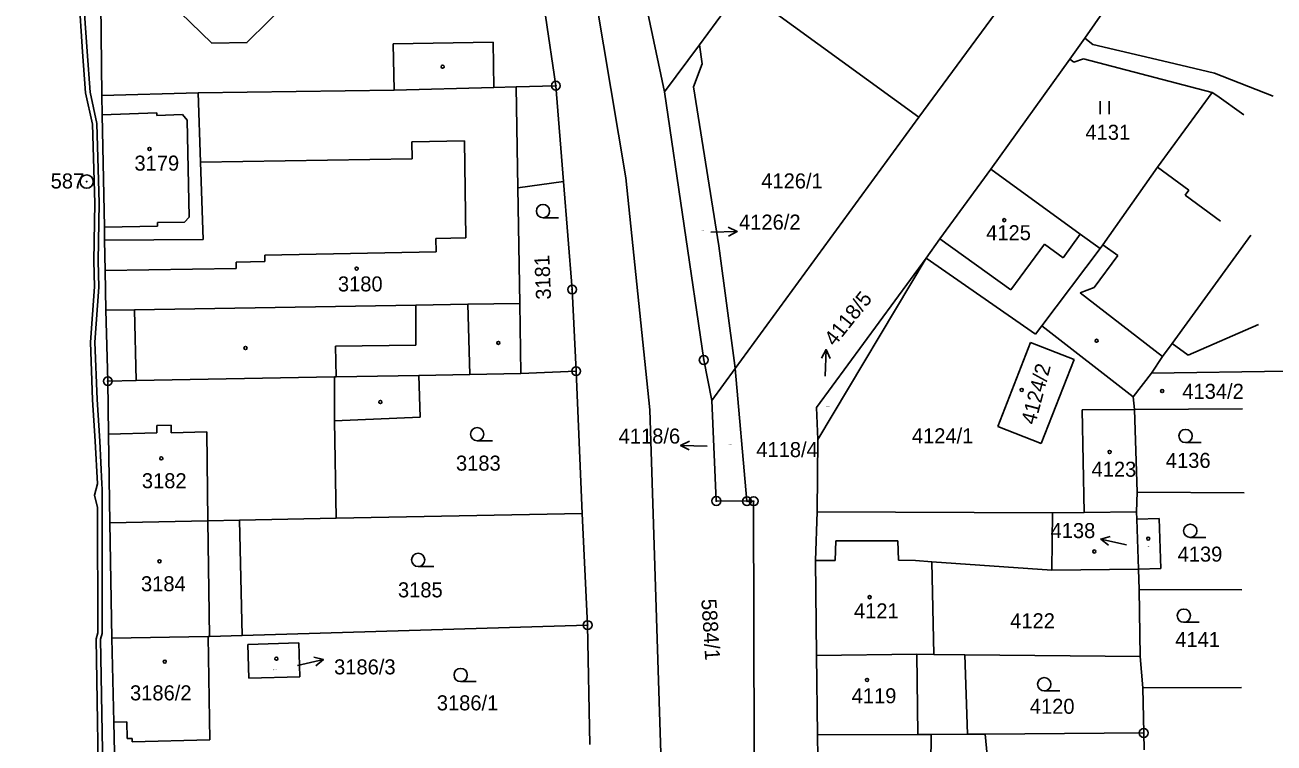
# Model space of a CAD drawing. Extents: x -735092 to -733385, y -1122435 to -1118992.
# Drawn here: x -734445.9 to -734304.7, y -1120246.4 to -1120165.2 of the extents above; entities that cross this region are included whole.
import ezdxf

# ---------------------------------------------------------------- set-up
doc = ezdxf.new("R2010")
doc.units = 0
for name, color, linetype in [('Vrstva 1', 7, 'Continuous'), ('Vrstva 10', 7, 'Continuous'), ('Vrstva 16', 7, 'Continuous'), ('Vrstva 17', 7, 'Continuous'), ('Vrstva 18', 7, 'Continuous'), ('Vrstva 19', 7, 'Continuous'), ('Vrstva 25', 7, 'Continuous'), ('Vrstva 27', 7, 'Continuous'), ('Vrstva 4', 7, 'Continuous')]:
    doc.layers.add(name, color=color, linetype=linetype)

msp = doc.modelspace()

# ---------------------------------------------------------------- linework, layer by layer
at = {"layer": 'Vrstva 1'}
for points in [[(-734388.19, -1120156.22), (-734385.85, -1120172.09)], [(-734377.07, -1120156.21), (-734373.55, -1120172.79)], [(-734369.62, -1120167.46), (-734364.89, -1120161.04)], [(-734364.89, -1120161.04), (-734344.83, -1120175.64)], [(-734437.28, -1120162.84), (-734437.16, -1120173.21)], [(-734344.83, -1120175.64), (-734335.61, -1120163.18)], [(-734326.04, -1120166.73), (-734323.79, -1120163.47)], [(-734373.55, -1120172.79), (-734369.62, -1120167.46)], [(-734369.62, -1120167.46), (-734369.29, -1120169.62)], [(-734327.74, -1120169.11), (-734326.04, -1120166.73)], [(-734326.04, -1120166.73), (-734325.13, -1120167.42)], [(-734325.13, -1120167.42), (-734316.63, -1120169.42)], [(-734336.67, -1120181.53), (-734327.74, -1120169.11)], [(-734327.74, -1120169.11), (-734327.31, -1120169.43)], [(-734327.31, -1120169.43), (-734326.19, -1120169.06)], [(-734326.19, -1120169.06), (-734311.66, -1120172.86)], [(-734369.29, -1120169.62), (-734370.29, -1120172.21)], [(-734316.63, -1120169.42), (-734311.38, -1120170.66)], [(-734311.38, -1120170.66), (-734304.75, -1120173.28)], [(-734390.34, -1120172.22), (-734385.85, -1120172.09)], [(-734385.85, -1120172.09), (-734384.98, -1120182.94)], [(-734437.16, -1120173.21), (-734426.3, -1120172.91)], [(-734437.16, -1120173.21), (-734437.13, -1120175.37)], [(-734426.3, -1120172.91), (-734404.13, -1120172.58)], [(-734426.3, -1120172.91), (-734426.02, -1120180.73)], [(-734404.13, -1120172.58), (-734392.87, -1120172.29)], [(-734392.87, -1120172.29), (-734390.34, -1120172.22)], [(-734373.55, -1120172.79), (-734369.13, -1120203.11)], [(-734370.29, -1120172.21), (-734367.41, -1120190.22)], [(-734317.82, -1120181.32), (-734311.66, -1120172.86)], [(-734311.66, -1120172.86), (-734311.14, -1120173.22)], [(-734311.14, -1120173.22), (-734308.07, -1120175.39)], [(-734437.13, -1120175.37), (-734436.88, -1120188.08)], [(-734365.59, -1120204.07), (-734344.83, -1120175.64)], [(-734426.02, -1120180.73), (-734425.71, -1120189.47)], [(-734342.45, -1120189.42), (-734336.67, -1120181.53)], [(-734336.67, -1120181.53), (-734326.56, -1120188.87)], [(-734324.02, -1120190.1), (-734317.82, -1120181.32)], [(-734390.15, -1120183.65), (-734384.98, -1120182.94)], [(-734384.98, -1120182.94), (-734384.01, -1120195.15)], [(-734390.15, -1120183.65), (-734389.94, -1120196.71)], [(-734436.88, -1120188.08), (-734436.86, -1120189.58)], [(-734326.56, -1120188.87), (-734324.31, -1120190.51)], [(-734316.19, -1120201.26), (-734307.27, -1120189.01)], [(-734436.86, -1120189.58), (-734425.71, -1120189.47)], [(-734436.86, -1120189.58), (-734436.79, -1120192.99)], [(-734367.41, -1120190.22), (-734365.63, -1120203.75)], [(-734344, -1120191.6), (-734342.45, -1120189.42)], [(-734330.9, -1120199.24), (-734324.31, -1120190.51)], [(-734324.31, -1120190.51), (-734324.02, -1120190.1)], [(-734356.4, -1120208.47), (-734344, -1120191.6)], [(-734356.22, -1120212.09), (-734344, -1120191.6)], [(-734344, -1120191.6), (-734331.62, -1120200.2)], [(-734436.79, -1120192.99), (-734436.71, -1120197.49)], [(-734384.01, -1120195.15), (-734383.56, -1120204.38)], [(-734436.71, -1120197.49), (-734436.5, -1120205.51)], [(-734389.94, -1120196.71), (-734389.81, -1120204.63)], [(-734331.62, -1120200.2), (-734330.9, -1120199.24)], [(-734330.9, -1120199.24), (-734320.57, -1120207.27)], [(-734314.36, -1120202.56), (-734306.41, -1120199.09)], [(-734335.88, -1120210.65), (-734332.2, -1120201.13)], [(-734332.2, -1120201.13), (-734327.26, -1120203.06)], [(-734317.26, -1120202.73), (-734316.19, -1120201.26)], [(-734316.19, -1120201.26), (-734314.36, -1120202.56)], [(-734369.13, -1120203.11), (-734368.23, -1120207.69)], [(-734330.97, -1120212.57), (-734327.26, -1120203.06)], [(-734318.52, -1120204.62), (-734317.26, -1120202.73)], [(-734395.58, -1120204.74), (-734389.81, -1120204.63)], [(-734389.81, -1120204.63), (-734383.56, -1120204.38)], [(-734383.56, -1120204.38), (-734382.86, -1120220.49)], [(-734368.23, -1120207.69), (-734365.59, -1120204.07)], [(-734365.63, -1120203.75), (-734365.59, -1120204.07)], [(-734364.25, -1120219.08), (-734365.59, -1120204.07)], [(-734320.57, -1120207.27), (-734318.52, -1120204.62)], [(-734318.52, -1120204.62), (-734303.17, -1120204.36)], [(-734436.5, -1120205.51), (-734433.3, -1120205.45)], [(-734436.5, -1120205.51), (-734436.41, -1120211.49)], [(-734433.3, -1120205.45), (-734410.88, -1120205.03)], [(-734410.88, -1120205.03), (-734410.69, -1120205.02)], [(-734410.69, -1120205.02), (-734401.34, -1120204.85)], [(-734401.34, -1120204.85), (-734395.58, -1120204.74)], [(-734401.34, -1120204.85), (-734401.18, -1120209.59)], [(-734320.57, -1120207.27), (-734320.45, -1120208.7)], [(-734368.23, -1120207.69), (-734367.71, -1120219.06)], [(-734356.4, -1120208.47), (-734356.22, -1120212.09)], [(-734326.34, -1120208.76), (-734320.45, -1120208.7)], [(-734326.34, -1120208.76), (-734326.14, -1120220.37)], [(-734320.45, -1120208.7), (-734308.22, -1120208.63)], [(-734320.45, -1120208.7), (-734320.14, -1120218.07)], [(-734410.88, -1120210), (-734401.18, -1120209.59)], [(-734410.88, -1120210), (-734410.68, -1120221.02)], [(-734436.41, -1120211.49), (-734436.26, -1120221.53)], [(-734335.88, -1120210.65), (-734330.97, -1120212.57)], [(-734356.3, -1120220.29), (-734356.22, -1120212.09)], [(-734320.2, -1120220.27), (-734320.14, -1120218.07)], [(-734320.14, -1120218.07), (-734308.03, -1120218.15)], [(-734367.71, -1120219.06), (-734364.25, -1120219.08)], [(-734364.25, -1120219.08), (-734363.49, -1120219.09)], [(-734363.49, -1120219.09), (-734363.36, -1120275.36)], [(-734436.26, -1120221.53), (-734425.18, -1120221.3)], [(-734436.26, -1120221.53), (-734436.06, -1120234.59)], [(-734425.18, -1120221.3), (-734421.63, -1120221.23)], [(-734421.63, -1120221.23), (-734410.68, -1120221.02)], [(-734421.63, -1120221.23), (-734421.33, -1120234.26)], [(-734410.68, -1120221.02), (-734382.86, -1120220.49)], [(-734382.86, -1120220.49), (-734382.26, -1120233.1)], [(-734356.51, -1120225.79), (-734356.3, -1120220.29)], [(-734356.3, -1120220.29), (-734329.69, -1120220.41)], [(-734329.69, -1120220.41), (-734326.14, -1120220.37)], [(-734326.14, -1120220.37), (-734320.2, -1120220.27)], [(-734320.2, -1120220.27), (-734320.17, -1120221.12)], [(-734320.17, -1120221.12), (-734317.65, -1120221.03)], [(-734320.17, -1120221.12), (-734319.98, -1120226.79)], [(-734317.65, -1120221.03), (-734317.46, -1120226.7)], [(-734356.51, -1120225.79), (-734356.37, -1120236.52)], [(-734343.34, -1120225.93), (-734343.11, -1120236.41)], [(-734343.34, -1120225.93), (-734329.78, -1120226.87)], [(-734329.78, -1120226.87), (-734319.98, -1120226.79)], [(-734319.98, -1120226.79), (-734317.46, -1120226.7)], [(-734319.98, -1120226.79), (-734319.9, -1120229.06)], [(-734319.9, -1120229.06), (-734319.8, -1120236.66)], [(-734319.9, -1120229.06), (-734308.29, -1120229.12)], [(-734425.01, -1120234.37), (-734421.33, -1120234.26)], [(-734421.33, -1120234.26), (-734382.26, -1120233.1)], [(-734382.26, -1120233.1), (-734381.99, -1120246.61)], [(-734436.06, -1120234.59), (-734425.16, -1120234.37)], [(-734436.06, -1120234.59), (-734435.82, -1120244.07)], [(-734425.16, -1120234.37), (-734425.01, -1120234.37)], [(-734425.16, -1120234.37), (-734424.97, -1120246.07)], [(-734420.68, -1120235.29), (-734414.89, -1120235.1)], [(-734420.68, -1120235.29), (-734420.57, -1120239.09)], [(-734414.89, -1120235.1), (-734414.78, -1120238.93)], [(-734356.37, -1120236.52), (-734345.04, -1120236.39)], [(-734356.37, -1120236.52), (-734356.26, -1120245.51)], [(-734345.04, -1120236.39), (-734343.11, -1120236.41)], [(-734343.11, -1120236.41), (-734339.6, -1120236.45)], [(-734339.6, -1120236.45), (-734319.8, -1120236.66)], [(-734339.6, -1120236.45), (-734339.32, -1120245.43)], [(-734319.8, -1120236.66), (-734319.48, -1120240.2)], [(-734420.57, -1120239.09), (-734414.78, -1120238.93)], [(-734319.48, -1120240.2), (-734308.35, -1120240.15)], [(-734319.48, -1120240.2), (-734319.39, -1120245.3)], [(-734435.82, -1120244.07), (-734434.35, -1120244.04)], [(-734435.82, -1120244.07), (-734435.73, -1120247.52)], [(-734434.35, -1120244.04), (-734434.31, -1120245.94)], [(-734356.26, -1120245.51), (-734344.93, -1120245.47)], [(-734356.26, -1120245.51), (-734356.25, -1120248.09)], [(-734344.93, -1120245.47), (-734343.43, -1120245.46)], [(-734343.43, -1120245.46), (-734339.32, -1120245.43)], [(-734339.32, -1120245.43), (-734337.32, -1120245.42)], [(-734337.32, -1120245.42), (-734319.39, -1120245.3)], [(-734337.32, -1120245.42), (-734337.02, -1120248.59)], [(-734319.39, -1120245.3), (-734319.34, -1120247.21)], [(-734434.31, -1120245.94), (-734433.74, -1120245.92)], [(-734433.74, -1120245.92), (-734433.73, -1120246.29)], [(-734433.73, -1120246.29), (-734424.97, -1120246.07)]]:
    msp.add_lwpolyline(points, dxfattribs=at)
at = {"layer": 'Vrstva 10'}
for points in [[(-734377.94, -1120182.5), (-734382.16, -1120157.32)], [(-734377.94, -1120182.5), (-734375.24, -1120208.76)], [(-734375.24, -1120208.76), (-734373.89, -1120249.96)]]:
    msp.add_lwpolyline(points, dxfattribs=at)
at = {"layer": 'Vrstva 25'}
for points in [[(-734324.317, -1120175.325), (-734324.317, -1120173.825)], [(-734323.283, -1120175.325), (-734323.283, -1120173.825)], [(-734387.3, -1120187.02), (-734385.55, -1120187.02)], [(-734368.34, -1120188.67), (-734365.342, -1120188.571)], [(-734366.358, -1120188.104), (-734365.342, -1120188.571), (-734366.325, -1120189.103)], [(-734355.829, -1120202.924), (-734355.296, -1120201.942), (-734354.831, -1120202.959)], [(-734355.4, -1120204.94), (-734355.296, -1120201.942)], [(-734394.75, -1120212.25), (-734393, -1120212.25)], [(-734370.763, -1120213.293), (-734371.748, -1120212.767), (-734370.735, -1120212.295)], [(-734368.75, -1120212.85), (-734371.748, -1120212.767)], [(-734314.66, -1120212.46), (-734312.91, -1120212.46)], [(-734323.38, -1120224.072), (-734324.251, -1120223.371), (-734323.167, -1120223.096)], [(-734321.32, -1120224.01), (-734324.251, -1120223.371)], [(-734314.13, -1120223.18), (-734312.38, -1120223.18)], [(-734401.41, -1120226.48), (-734399.66, -1120226.48)], [(-734314.86, -1120232.78), (-734313.11, -1120232.78)], [(-734415.04, -1120237.68), (-734412.125, -1120236.975)], [(-734413.214, -1120236.724), (-734412.125, -1120236.975), (-734412.979, -1120237.695)], [(-734396.61, -1120239.49), (-734394.86, -1120239.49)], [(-734330.63, -1120240.54), (-734328.88, -1120240.54)]]:
    msp.add_lwpolyline(points, dxfattribs=at)
for centre, radius in [((-734398.65, -1120169.95), 0.175), ((-734385.85, -1120172.09), 0.499), ((-734385.85, -1120172.09), 0.0314), ((-734431.79, -1120179.25), 0.175), ((-734438.89, -1120182.94), 0.75), ((-734438.89, -1120182.94), 0.032), ((-734387.3, -1120186.27), 0.75), ((-734335.16, -1120187.3), 0.175), ((-734408.37, -1120192.78), 0.175), ((-734384.01, -1120195.15), 0.499), ((-734384.01, -1120195.15), 0.0318), ((-734420.93, -1120201.76), 0.175), ((-734392.35, -1120201.18), 0.175), ((-734324.71, -1120200.94), 0.175), ((-734369.13, -1120203.11), 0.5), ((-734369.13, -1120203.11), 0.032), ((-734383.56, -1120204.38), 0.5), ((-734383.56, -1120204.38), 0.5), ((-734383.56, -1120204.38), 0.032), ((-734383.56, -1120204.38), 0.032), ((-734436.5, -1120205.51), 0.5), ((-734436.5, -1120205.51), 0.032), ((-734333.18, -1120206.5), 0.175), ((-734317.3, -1120206.63), 0.175), ((-734405.69, -1120207.87), 0.175), ((-734394.75, -1120211.5), 0.75), ((-734314.66, -1120211.71), 0.75), ((-734430.46, -1120214.24), 0.175), ((-734323.25, -1120213.52), 0.175), ((-734367.71, -1120219.06), 0.5), ((-734364.25, -1120219.08), 0.5), ((-734363.49, -1120219.09), 0.5), ((-734367.71, -1120219.06), 0.032), ((-734364.25, -1120219.08), 0.032), ((-734363.49, -1120219.09), 0.032), ((-734314.13, -1120222.43), 0.75), ((-734318.88, -1120223.32), 0.175), ((-734430.66, -1120225.88), 0.175), ((-734401.41, -1120225.73), 0.75), ((-734324.98, -1120224.77), 0.175), ((-734350.38, -1120229.94), 0.175), ((-734314.86, -1120232.03), 0.75), ((-734382.26, -1120233.1), 0.5), ((-734382.26, -1120233.1), 0.032), ((-734430.06, -1120237.23), 0.175), ((-734417.44, -1120236.9), 0.175), ((-734396.61, -1120238.74), 0.75), ((-734350.67, -1120239.3), 0.175), ((-734330.63, -1120239.79), 0.75), ((-734319.39, -1120245.3), 0.5), ((-734319.39, -1120245.3), 0.032)]:
    msp.add_circle(centre, radius, dxfattribs=at)
at = {"layer": 'Vrstva 27'}
for points in [[(-734439.35, -1120168.27), (-734439.79, -1120161.82), (-734440.17, -1120157.57), (-734440.42, -1120155.71), (-734440.49, -1120153.95), (-734440.81, -1120150.87), (-734441, -1120143.71), (-734441.33, -1120139.3), (-734441.45, -1120137.78), (-734440.57, -1120127.65), (-734439.16, -1120121.9), (-734437.39, -1120117.67), (-734445.19, -1120117), (-734445.16, -1120115.89), (-734445.33, -1120114.9), (-734444.93, -1120112.5), (-734443.79, -1120107.82), (-734443.49, -1120106.95), (-734442.89, -1120105.24), (-734442.89, -1120103.52), (-734443.84, -1120102.38), (-734458.64, -1120099.24)], [(-734439.29, -1120161.78), (-734438.85, -1120168.23), (-734438.51, -1120172.83), (-734437.75, -1120176.38), (-734437.46, -1120185.39), (-734437.58, -1120191.9), (-734437.51, -1120194.87), (-734437.95, -1120201.1), (-734437.72, -1120207.59), (-734437.42, -1120212.29), (-734437.17, -1120217.11), (-734437.15, -1120217.71), (-734437.15, -1120219.78), (-734437.14, -1120234.04), (-734437.32, -1120234.7), (-734436.96, -1120255.72)], [(-734437.46, -1120255.76), (-734437.82, -1120234.64), (-734437.64, -1120233.98), (-734437.65, -1120219.81), (-734437.99, -1120218.42), (-734437.67, -1120217.11), (-734437.92, -1120212.31), (-734438.22, -1120207.61), (-734438.45, -1120201.1), (-734438.01, -1120194.85), (-734438.08, -1120191.9), (-734437.96, -1120185.39), (-734438.25, -1120176.44), (-734439.01, -1120172.91), (-734439.35, -1120168.27)]]:
    msp.add_lwpolyline(points, dxfattribs=at)
at = {"layer": 'Vrstva 4'}
for points in [[(-734437.28, -1120162.84), (-734429.54, -1120162.63), (-734424.75, -1120167.27), (-734420.77, -1120167.21), (-734415.87, -1120162.33), (-734393.1, -1120161.94)], [(-734404.23, -1120167.35), (-734392.94, -1120167.18)], [(-734404.23, -1120167.35), (-734404.13, -1120172.58)], [(-734392.94, -1120167.18), (-734392.87, -1120172.29)], [(-734390.34, -1120172.22), (-734390.15, -1120183.65)], [(-734437.13, -1120175.37), (-734430.96, -1120175.15)], [(-734430.96, -1120175.15), (-734430.95, -1120175.46)], [(-734430.95, -1120175.46), (-734428.07, -1120175.36)], [(-734428.07, -1120175.36), (-734427.54, -1120175.99)], [(-734427.54, -1120175.99), (-734427.32, -1120186.96)], [(-734402.14, -1120178.45), (-734396.16, -1120178.34)], [(-734402.14, -1120178.45), (-734402.11, -1120180.35)], [(-734396.16, -1120178.34), (-734396.01, -1120189.29)], [(-734426.02, -1120180.73), (-734402.11, -1120180.35)], [(-734317.82, -1120181.32), (-734314.29, -1120183.89)], [(-734314.72, -1120184.48), (-734314.29, -1120183.89)], [(-734314.72, -1120184.48), (-734310.7, -1120187.41)], [(-734430.9, -1120187.57), (-734427.82, -1120187.52)], [(-734430.9, -1120187.57), (-734430.89, -1120187.97)], [(-734427.82, -1120187.52), (-734427.32, -1120186.96)], [(-734436.88, -1120188.08), (-734430.89, -1120187.97)], [(-734328.51, -1120191.56), (-734326.56, -1120188.87)], [(-734399.41, -1120189.36), (-734396.01, -1120189.29)], [(-734399.41, -1120189.36), (-734399.38, -1120190.87)], [(-734342.45, -1120189.42), (-734334.42, -1120195.18)], [(-734334.42, -1120195.18), (-734330.61, -1120190.03)], [(-734330.61, -1120190.03), (-734328.51, -1120191.56)], [(-734324.02, -1120190.1), (-734322.31, -1120191.31)], [(-734418.76, -1120191.25), (-734399.38, -1120190.87)], [(-734418.76, -1120191.25), (-734418.75, -1120191.99)], [(-734324.99, -1120194.9), (-734322.31, -1120191.31)], [(-734436.79, -1120192.99), (-734421.99, -1120192.76)], [(-734422, -1120192.06), (-734418.75, -1120191.99)], [(-734422, -1120192.06), (-734421.99, -1120192.76)], [(-734326.58, -1120195.52), (-734324.99, -1120194.9)], [(-734326.58, -1120195.52), (-734317.26, -1120202.73)], [(-734436.71, -1120197.49), (-734433.49, -1120197.44)], [(-734433.49, -1120197.44), (-734401.66, -1120196.91)], [(-734433.49, -1120197.44), (-734433.3, -1120205.45)], [(-734401.69, -1120201.44), (-734401.66, -1120196.91)], [(-734401.66, -1120196.91), (-734395.8, -1120196.81)], [(-734395.8, -1120196.81), (-734389.94, -1120196.71)], [(-734395.8, -1120196.81), (-734395.58, -1120204.74)], [(-734410.75, -1120201.55), (-734401.69, -1120201.44)], [(-734410.75, -1120201.55), (-734410.69, -1120205.02)], [(-734410.88, -1120205.03), (-734410.88, -1120210)], [(-734436.41, -1120211.49), (-734430.96, -1120211.37)], [(-734430.97, -1120210.51), (-734429.34, -1120210.47)], [(-734430.97, -1120210.51), (-734430.96, -1120211.37)], [(-734429.34, -1120210.47), (-734429.32, -1120211.34)], [(-734429.32, -1120211.34), (-734425.31, -1120211.25)], [(-734425.31, -1120211.25), (-734425.18, -1120221.3)], [(-734425.18, -1120221.3), (-734425.01, -1120234.37)], [(-734329.78, -1120226.87), (-734329.69, -1120220.41)], [(-734354.28, -1120225.79), (-734354.21, -1120223.58)], [(-734354.21, -1120223.58), (-734347.17, -1120223.56)], [(-734347.17, -1120223.56), (-734347.1, -1120225.77)], [(-734356.51, -1120225.79), (-734354.28, -1120225.79)], [(-734347.1, -1120225.77), (-734345.18, -1120225.8)], [(-734345.18, -1120225.8), (-734343.34, -1120225.93)], [(-734345.04, -1120236.39), (-734344.93, -1120245.47)], [(-734343.44, -1120248.82), (-734343.43, -1120245.46)]]:
    msp.add_lwpolyline(points, dxfattribs=at)

# ---------------------------------------------------------------- texts
at = {"layer": 'Vrstva 16'}
for s, p in [('4126/2', (-734365.14, -1120188.37)), ('4118/6', (-734378.747, -1120212.57)), ('4138', (-734329.926, -1120223.26)), ('3186/3', (-734410.92, -1120238.67))]:
    msp.add_text(s, height=1.7, dxfattribs=at).set_placement(p)
for s, rotation, p in [('4118/5', 51.50041, (-734354.332, -1120201.659)), ('5884/1', 273.80218, (-734369.415, -1120230.187))]:
    msp.add_text(s, height=1.7, rotation=rotation, dxfattribs=at).set_placement(p)
at = {"layer": 'Vrstva 17'}
msp.add_text('587', height=1.7, dxfattribs=at).set_placement((-734442.96, -1120183.72))
at = {"layer": 'Vrstva 18'}
for s, height, p in [('4131', 1.7, (-734325.98, -1120178.21)), ('4126/1', 1.7, (-734362.63, -1120183.71)), ('4126/2', 0.1, (-734369.53, -1120188.52)), ('4118/5', 0.1, (-734355.33, -1120208.43)), ('4124/1', 1.7, (-734345.6, -1120212.54)), ('4118/6', 0.1, (-734366.34, -1120212.71)), ('4118/4', 1.7, (-734363.19, -1120214.1)), ('3183', 1.7, (-734397.14, -1120215.63)), ('4136', 1.7, (-734316.89, -1120215.32)), ('4139', 1.7, (-734315.56, -1120225.92)), ('3185', 1.7, (-734403.7, -1120229.96)), ('4122', 1.7, (-734334.49, -1120233.46)), ('4141', 1.7, (-734315.83, -1120235.58)), ('3186/1', 1.7, (-734399.31, -1120242.74)), ('4120', 1.7, (-734332.27, -1120243.13))]:
    msp.add_text(s, height=height, dxfattribs=at).set_placement(p)
msp.add_text('3181', height=1.7, rotation=92.30073, dxfattribs=at).set_placement((-734386.387, -1120196.259))
at = {"layer": 'Vrstva 19'}
for s, height, p in [('3179', 1.7, (-734433.49, -1120181.7)), ('4125', 1.7, (-734337.2, -1120189.57)), ('3180', 1.7, (-734410.49, -1120195.36)), ('4134/2', 1.7, (-734315.03, -1120207.51)), ('3182', 1.7, (-734432.65, -1120217.62)), ('4123', 1.7, (-734325.29, -1120216.32)), ('4138', 0.1, (-734319.07, -1120224.26)), ('3184', 1.7, (-734432.75, -1120229.27)), ('4121', 1.7, (-734352.15, -1120232.34)), ('3186/3', 0.1, (-734417.85, -1120238.21)), ('3186/2', 1.7, (-734433.99, -1120241.61)), ('4119', 1.7, (-734352.41, -1120241.94))]:
    msp.add_text(s, height=height, dxfattribs=at).set_placement(p)
msp.add_text('4124/2', height=1.7, rotation=75.2006, dxfattribs=at).set_placement((-734331.652, -1120210.516))

doc.saveas('drawing.dxf')
